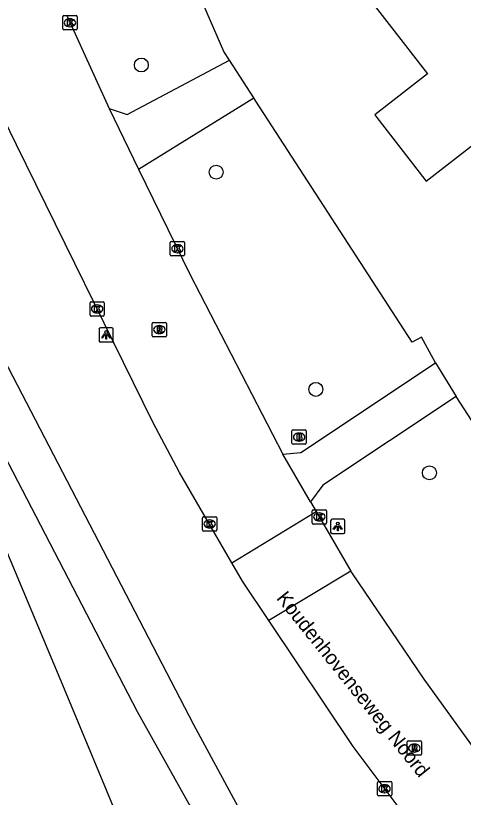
# Model space of a CAD drawing. Extents: x 162417 to 163721, y 384268 to 385416.
# Drawn here: x 163351.6 to 163382.9, y 384915.5 to 384970.3 of the extents above; entities that cross this region are included whole.
import ezdxf

# ---------------------------------------------------------------- set-up
doc = ezdxf.new("R2010")
doc.units = 0
for name, color, linetype in [('IMGEO_Boom', 7, 'Continuous'), ('IMGEO_Brandkraan', 7, 'Continuous'), ('IMGEO_Groenvoorziening', 7, 'Continuous'), ('IMGEO_Kolk', 7, 'Continuous'), ('IMGEO_Lichtpunt', 7, 'Continuous'), ('IMGEO_Loofbos', 7, 'Continuous'), ('IMGEO_Openbare_ruimte_label', 7, 'Continuous'), ('IMGEO_Pand', 7, 'Continuous'), ('IMGEO_Rijbaan_lokaal_gesloten', 7, 'Continuous'), ('IMGEO_Rijbaan_lokaal_open', 7, 'Continuous'), ('IMGEO_Rioolput', 7, 'Continuous'), ('IMGEO_Voetpad_open', 7, 'Continuous')]:
    doc.layers.add(name, color=color, linetype=linetype)

msp = doc.modelspace()

# ---------------------------------------------------------------- linework, layer by layer
at = {"layer": 'IMGEO_Boom'}
for centre in [(163360.375, 384966.821), (163365.617, 384959.319), (163372.593, 384944.113), (163380.546, 384938.265)]:
    msp.add_circle(centre, 0.489, dxfattribs=at)
at = {"layer": 'IMGEO_Brandkraan'}
for p, q in [((163370.923, 384940.346), (163370.923, 384941.198)), ((163370.998, 384941.272), (163371.85, 384941.272)), ((163371.924, 384941.198), (163371.924, 384940.346)), ((163371.411, 384941.052), (163371.436, 384941.052)), ((163371.85, 384940.272), (163370.998, 384940.272)), ((163371.434, 384940.492), (163371.409, 384940.492))]:
    msp.add_line(p, q, dxfattribs=at)
for points in [[(163370.923, 384940.346), (163370.923, 384941.198)], [(163370.998, 384941.272), (163371.85, 384941.272)], [(163371.924, 384941.198), (163371.924, 384940.346)], [(163371.271, 384940.972), (163371.271, 384940.572), (163371.484, 384940.572)], [(163371.502, 384940.972), (163371.271, 384940.972)], [(163371.45, 384940.891), (163371.396, 384940.891), (163371.396, 384940.815)], [(163371.396, 384940.815), (163371.449, 384940.815)], [(163371.458, 384940.739), (163371.396, 384940.739), (163371.396, 384940.658)], [(163371.396, 384940.658), (163371.458, 384940.658)], [(163371.85, 384940.272), (163370.998, 384940.272)]]:
    msp.add_lwpolyline(points, dxfattribs=at)
for centre, radius, start, end in [((163371, 384941.196), 0.0765, 91.552, 178.448), ((163371, 384941.196), 0.0765, 91.552, 178.448), ((163371.848, 384941.196), 0.0765, 1.552, 88.448), ((163371.848, 384941.196), 0.0765, 1.552, 88.448), ((163371.451, 384940.853), 0.0379, 267.8285, 90.9355), ((163371.459, 384940.698), 0.0404, 269.8759, 90.5077), ((163371.49, 384940.823), 0.251, 268.6676, 293.5347), ((163371.506, 384940.827), 0.145, 59.4692, 91.5367), ((163371.531, 384940.874), 0.0922, 285.5137, 58.1501), ((163371.536, 384940.682), 0.105, 301.3115, 78.989), ((163371, 384940.348), 0.0765, 181.552, 268.448), ((163371, 384940.348), 0.0765, 181.552, 268.448), ((163371.848, 384940.348), 0.0765, 271.552, 358.448), ((163371.848, 384940.348), 0.0765, 271.552, 358.448)]:
    msp.add_arc(centre, radius, start, end, dxfattribs=at)
for centre, major_axis, ratio, start_param, end_param in [((163371.41, 384940.772), (-0.387, 0.002), 0.722429, 4.712389, 7.853982), ((163371.435, 384940.772), (-0.39, 0.002), 0.717154, 1.570796, 4.712389)]:
    msp.add_ellipse(centre, major_axis=major_axis, ratio=ratio, start_param=start_param, end_param=end_param, dxfattribs=at)
at = {"layer": 'IMGEO_Groenvoorziening'}
for points in [[(163366.55, 384967.171), (163366.161, 384967.778), (163363.507, 384973.847)], [(163380.971, 384945.978), (163379.982, 384947.768), (163379.349, 384947.426), (163368.391, 384964.299), (163368.242, 384964.531)], [(163394.29, 384925.305), (163382.418, 384943.603)]]:
    msp.add_lwpolyline(points, dxfattribs=at)
at = {"layer": 'IMGEO_Kolk'}
for p, q in [((163354.878, 384969.351), (163354.878, 384970.203)), ((163354.953, 384970.277), (163355.805, 384970.277)), ((163355.879, 384970.203), (163355.879, 384969.351)), ((163355.366, 384970.057), (163355.391, 384970.057)), ((163355.805, 384969.277), (163354.953, 384969.277)), ((163355.389, 384969.497), (163355.364, 384969.497)), ((163362.402, 384953.535), (163362.402, 384954.387)), ((163362.477, 384954.461), (163363.329, 384954.461)), ((163362.89, 384954.241), (163362.915, 384954.241)), ((163363.403, 384954.387), (163363.403, 384953.535)), ((163362.913, 384953.681), (163362.888, 384953.681)), ((163363.329, 384953.461), (163362.477, 384953.461)), ((163356.782, 384949.319), (163356.782, 384950.171)), ((163356.857, 384950.245), (163357.709, 384950.245)), ((163357.27, 384950.025), (163357.295, 384950.025)), ((163357.783, 384950.171), (163357.783, 384949.319)), ((163357.293, 384949.465), (163357.268, 384949.465)), ((163357.709, 384949.245), (163356.857, 384949.245)), ((163372.339, 384934.758), (163372.339, 384935.61)), ((163372.414, 384935.684), (163373.266, 384935.684)), ((163373.34, 384935.61), (163373.34, 384934.758)), ((163364.659, 384934.268), (163364.659, 384935.12)), ((163364.734, 384935.194), (163365.586, 384935.194)), ((163365.66, 384935.12), (163365.66, 384934.268)), ((163372.827, 384935.464), (163372.852, 384935.464)), ((163365.147, 384934.974), (163365.172, 384934.974)), ((163373.266, 384934.684), (163372.414, 384934.684)), ((163372.85, 384934.904), (163372.825, 384934.904)), ((163365.586, 384934.194), (163364.734, 384934.194)), ((163365.17, 384934.414), (163365.145, 384934.414)), ((163376.903, 384915.727), (163376.903, 384916.579)), ((163376.978, 384916.653), (163377.83, 384916.653)), ((163377.904, 384916.579), (163377.904, 384915.727)), ((163377.391, 384916.433), (163377.416, 384916.433)), ((163377.83, 384915.653), (163376.978, 384915.653)), ((163377.414, 384915.873), (163377.389, 384915.873))]:
    msp.add_line(p, q, dxfattribs=at)
for points in [[(163354.878, 384969.351), (163354.878, 384970.203)], [(163354.953, 384970.277), (163355.805, 384970.277)], [(163355.879, 384970.203), (163355.879, 384969.351)], [(163355.199, 384969.977), (163355.322, 384969.977), (163355.322, 384969.826), (163355.452, 384969.977), (163355.616, 384969.977), (163355.47, 384969.826), (163355.623, 384969.577), (163355.471, 384969.577), (163355.386, 384969.741), (163355.322, 384969.674), (163355.322, 384969.577), (163355.199, 384969.577), (163355.199, 384969.977)], [(163355.805, 384969.277), (163354.953, 384969.277)], [(163362.402, 384953.535), (163362.402, 384954.387)], [(163362.477, 384954.461), (163363.329, 384954.461)], [(163363.403, 384954.387), (163363.403, 384953.535)], [(163362.723, 384954.161), (163362.846, 384954.161), (163362.846, 384954.01), (163362.976, 384954.161), (163363.14, 384954.161), (163362.994, 384954.01), (163363.147, 384953.761), (163362.995, 384953.761), (163362.91, 384953.925), (163362.846, 384953.858), (163362.846, 384953.761), (163362.723, 384953.761), (163362.723, 384954.161)], [(163363.329, 384953.461), (163362.477, 384953.461)], [(163356.782, 384949.319), (163356.782, 384950.171)], [(163356.857, 384950.245), (163357.709, 384950.245)], [(163357.103, 384949.945), (163357.226, 384949.945), (163357.226, 384949.794), (163357.356, 384949.945), (163357.52, 384949.945), (163357.374, 384949.794), (163357.527, 384949.545), (163357.375, 384949.545), (163357.29, 384949.709), (163357.226, 384949.642), (163357.226, 384949.545), (163357.103, 384949.545), (163357.103, 384949.945)], [(163357.783, 384950.171), (163357.783, 384949.319)], [(163357.709, 384949.245), (163356.857, 384949.245)], [(163372.339, 384934.758), (163372.339, 384935.61)], [(163372.414, 384935.684), (163373.266, 384935.684)], [(163373.34, 384935.61), (163373.34, 384934.758)], [(163364.659, 384934.268), (163364.659, 384935.12)], [(163364.734, 384935.194), (163365.586, 384935.194)], [(163365.66, 384935.12), (163365.66, 384934.268)], [(163372.66, 384935.384), (163372.783, 384935.384), (163372.783, 384935.233), (163372.913, 384935.384), (163373.077, 384935.384), (163372.931, 384935.233), (163373.084, 384934.984), (163372.932, 384934.984), (163372.847, 384935.148), (163372.783, 384935.081), (163372.783, 384934.984), (163372.66, 384934.984), (163372.66, 384935.384)], [(163364.98, 384934.894), (163365.103, 384934.894), (163365.103, 384934.743), (163365.233, 384934.894), (163365.397, 384934.894), (163365.251, 384934.743), (163365.404, 384934.494), (163365.252, 384934.494), (163365.167, 384934.658), (163365.103, 384934.591), (163365.103, 384934.494), (163364.98, 384934.494), (163364.98, 384934.894)], [(163373.266, 384934.684), (163372.414, 384934.684)], [(163365.586, 384934.194), (163364.734, 384934.194)], [(163376.903, 384915.727), (163376.903, 384916.579)], [(163376.978, 384916.653), (163377.83, 384916.653)], [(163377.904, 384916.579), (163377.904, 384915.727)], [(163377.224, 384916.353), (163377.347, 384916.353), (163377.347, 384916.202), (163377.477, 384916.353), (163377.641, 384916.353), (163377.495, 384916.202), (163377.648, 384915.953), (163377.496, 384915.953), (163377.411, 384916.117), (163377.347, 384916.05), (163377.347, 384915.953), (163377.224, 384915.953), (163377.224, 384916.353)], [(163377.83, 384915.653), (163376.978, 384915.653)]]:
    msp.add_lwpolyline(points, dxfattribs=at)
for centre, start, end in [((163354.955, 384970.201), 91.552, 178.448), ((163354.955, 384970.201), 91.552, 178.448), ((163355.803, 384970.201), 1.552, 88.448), ((163355.803, 384970.201), 1.552, 88.448), ((163354.955, 384969.353), 181.552, 268.448), ((163354.955, 384969.353), 181.552, 268.448), ((163355.803, 384969.353), 271.552, 358.448), ((163355.803, 384969.353), 271.552, 358.448), ((163362.479, 384954.385), 91.552, 178.448), ((163362.479, 384954.385), 91.552, 178.448), ((163363.327, 384954.385), 1.552, 88.448), ((163363.327, 384954.385), 1.552, 88.448), ((163362.479, 384953.537), 181.552, 268.448), ((163362.479, 384953.537), 181.552, 268.448), ((163363.327, 384953.537), 271.552, 358.448), ((163363.327, 384953.537), 271.552, 358.448), ((163356.859, 384950.169), 91.552, 178.448), ((163356.859, 384950.169), 91.552, 178.448), ((163357.707, 384950.169), 1.552, 88.448), ((163357.707, 384950.169), 1.552, 88.448), ((163356.859, 384949.321), 181.552, 268.448), ((163356.859, 384949.321), 181.552, 268.448), ((163357.707, 384949.321), 271.552, 358.448), ((163357.707, 384949.321), 271.552, 358.448), ((163372.416, 384935.608), 91.552, 178.448), ((163372.416, 384935.608), 91.552, 178.448), ((163373.264, 384935.608), 1.552, 88.448), ((163373.264, 384935.608), 1.552, 88.448), ((163364.736, 384935.118), 91.552, 178.448), ((163364.736, 384935.118), 91.552, 178.448), ((163365.584, 384935.118), 1.552, 88.448), ((163365.584, 384935.118), 1.552, 88.448), ((163372.416, 384934.76), 181.552, 268.448), ((163372.416, 384934.76), 181.552, 268.448), ((163373.264, 384934.76), 271.552, 358.448), ((163373.264, 384934.76), 271.552, 358.448), ((163364.736, 384934.27), 181.552, 268.448), ((163364.736, 384934.27), 181.552, 268.448), ((163365.584, 384934.27), 271.552, 358.448), ((163365.584, 384934.27), 271.552, 358.448), ((163376.98, 384916.577), 91.552, 178.448), ((163376.98, 384916.577), 91.552, 178.448), ((163377.828, 384916.577), 1.552, 88.448), ((163377.828, 384916.577), 1.552, 88.448), ((163376.98, 384915.729), 181.552, 268.448), ((163376.98, 384915.729), 181.552, 268.448), ((163377.828, 384915.729), 271.552, 358.448), ((163377.828, 384915.729), 271.552, 358.448)]:
    msp.add_arc(centre, 0.0765, start, end, dxfattribs=at)
for centre, major_axis, ratio, start_param, end_param in [((163355.365, 384969.777), (-0.387, 0.002), 0.722429, 4.712389, 7.853982), ((163355.39, 384969.777), (-0.39, 0.002), 0.717154, 1.570796, 4.712389), ((163362.889, 384953.961), (-0.387, 0.002), 0.722429, 4.712389, 7.853982), ((163362.914, 384953.961), (-0.39, 0.002), 0.717154, 1.570796, 4.712389), ((163357.269, 384949.745), (-0.387, 0.002), 0.722429, 4.712389, 7.853982), ((163357.294, 384949.745), (-0.39, 0.002), 0.717154, 1.570796, 4.712389), ((163372.826, 384935.184), (-0.387, 0.002), 0.722429, 4.712389, 7.853982), ((163372.851, 384935.184), (-0.39, 0.002), 0.717154, 1.570796, 4.712389), ((163365.146, 384934.694), (-0.387, 0.002), 0.722429, 4.712389, 7.853982), ((163365.171, 384934.694), (-0.39, 0.002), 0.717154, 1.570796, 4.712389), ((163377.39, 384916.153), (-0.387, 0.002), 0.722429, 4.712389, 7.853982), ((163377.415, 384916.153), (-0.39, 0.002), 0.717154, 1.570796, 4.712389)]:
    msp.add_ellipse(centre, major_axis=major_axis, ratio=ratio, start_param=start_param, end_param=end_param, dxfattribs=at)
at = {"layer": 'IMGEO_Lichtpunt'}
for p, q in [((163357.412, 384948.33), (163357.412, 384947.523)), ((163357.412, 384948.33), (163357.412, 384947.523)), ((163358.314, 384948.425), (163357.506, 384948.425)), ((163358.314, 384948.425), (163357.506, 384948.425)), ((163358.408, 384947.523), (163358.408, 384948.33)), ((163358.408, 384947.523), (163358.408, 384948.33)), ((163357.506, 384947.429), (163358.314, 384947.429)), ((163357.506, 384947.429), (163358.314, 384947.429)), ((163373.629, 384934.919), (163373.629, 384934.112)), ((163373.629, 384934.919), (163373.629, 384934.112)), ((163374.531, 384935.014), (163373.723, 384935.014)), ((163374.531, 384935.014), (163373.723, 384935.014)), ((163374.625, 384934.112), (163374.625, 384934.919)), ((163374.625, 384934.112), (163374.625, 384934.919)), ((163373.723, 384934.018), (163374.531, 384934.018)), ((163373.723, 384934.018), (163374.531, 384934.018))]:
    msp.add_line(p, q, dxfattribs=at)
for points in [[(163357.786, 384947.994), (163357.825, 384947.966), (163357.637, 384947.704), (163357.599, 384947.731), (163357.786, 384947.994)], [(163357.888, 384947.946), (163357.935, 384947.946), (163357.935, 384947.624), (163357.888, 384947.624), (163357.888, 384947.946)], [(163357.998, 384947.966), (163358.036, 384947.993), (163358.223, 384947.731), (163358.184, 384947.703), (163357.998, 384947.966)], [(163374.003, 384934.583), (163374.042, 384934.555), (163373.854, 384934.293), (163373.816, 384934.32), (163374.003, 384934.583)], [(163374.105, 384934.535), (163374.152, 384934.535), (163374.152, 384934.213), (163374.105, 384934.213), (163374.105, 384934.535)], [(163374.215, 384934.555), (163374.253, 384934.582), (163374.44, 384934.32), (163374.401, 384934.292), (163374.215, 384934.555)]]:
    msp.add_lwpolyline(points, dxfattribs=at)
for centre in [(163357.911, 384948.128), (163374.128, 384934.717)]:
    msp.add_circle(centre, 0.0994, dxfattribs=at)
for centre, start, end in [((163357.506, 384948.33), 90, 180), ((163357.506, 384948.33), 90, 180), ((163358.314, 384948.33), 0, 90), ((163358.314, 384948.33), 0, 90), ((163357.506, 384947.523), 180, 270), ((163357.506, 384947.523), 180, 270), ((163358.314, 384947.523), 270, 0), ((163358.314, 384947.523), 270, 360), ((163373.723, 384934.919), 90, 180), ((163373.723, 384934.919), 90, 180), ((163374.531, 384934.919), 0, 90), ((163374.531, 384934.919), 0, 90), ((163373.723, 384934.112), 180, 270), ((163373.723, 384934.112), 180, 270), ((163374.531, 384934.112), 270, 0), ((163374.531, 384934.112), 270, 360)]:
    msp.add_arc(centre, 0.0946, start, end, dxfattribs=at)
at = {"layer": 'IMGEO_Loofbos'}
msp.add_lwpolyline([(163370.337, 384886.24), (163355.108, 384922.849), (163338.205, 384963.202)], dxfattribs=at)
at = {"layer": 'IMGEO_Pand'}
msp.add_lwpolyline([(163383.993, 384961.544), (163389.969, 384966.169), (163389.817, 384966.363), (163387.465, 384969.38), (163391.542, 384972.558), (163385.708, 384980.043), (163381.669, 384976.895), (163381.023, 384977.723), (163380.856, 384977.937), (163374.9, 384973.327), (163375.046, 384973.139), (163380.414, 384966.203), (163376.718, 384963.343), (163376.874, 384963.141), (163380.225, 384958.812), (163380.314, 384958.697), (163383.993, 384961.544)], dxfattribs=at)
at = {"layer": 'IMGEO_Rijbaan_lokaal_gesloten'}
for points in [[(163355.13, 384970.334), (163358.119, 384963.778)], [(163366.713, 384931.978), (163363.047, 384938.292), (163361.182, 384941.826), (163351.64, 384961.227), (163348.551, 384967.508)], [(163358.119, 384963.778), (163360.184, 384959.531)], [(163360.184, 384959.531), (163363.764, 384952.168), (163370.281, 384939.578)], [(163372.231, 384936.23), (163370.281, 384939.578)], [(163372.231, 384936.23), (163372.616, 384935.569)], [(163383.749, 384918.881), (163380.184, 384923.814), (163375.106, 384931.292), (163375.046, 384931.395)], [(163387.873, 384902.747), (163381.659, 384910.522), (163375.211, 384919.101), (163369.3, 384927.939)]]:
    msp.add_lwpolyline(points, dxfattribs=at)
at = {"layer": 'IMGEO_Rijbaan_lokaal_open'}
for points in [[(163366.713, 384931.978), (163372.616, 384935.569)], [(163372.616, 384935.569), (163375.046, 384931.395)], [(163369.3, 384927.939), (163367.462, 384930.688), (163366.713, 384931.978)], [(163375.046, 384931.395), (163369.3, 384927.939)]]:
    msp.add_lwpolyline(points, dxfattribs=at)
at = {"layer": 'IMGEO_Rioolput'}
for p, q in [((163361.212, 384948.795), (163362.064, 384948.795)), ((163361.137, 384947.869), (163361.137, 384948.721)), ((163361.625, 384948.575), (163361.65, 384948.575)), ((163362.138, 384948.721), (163362.138, 384947.869)), ((163362.064, 384947.795), (163361.212, 384947.795)), ((163361.648, 384948.015), (163361.623, 384948.015)), ((163378.991, 384918.574), (163378.991, 384919.426)), ((163379.066, 384919.5), (163379.918, 384919.5)), ((163379.479, 384919.28), (163379.504, 384919.28)), ((163379.992, 384919.426), (163379.992, 384918.574)), ((163379.502, 384918.72), (163379.477, 384918.72)), ((163379.918, 384918.5), (163379.066, 384918.5))]:
    msp.add_line(p, q, dxfattribs=at)
for points in [[(163361.212, 384948.795), (163362.064, 384948.795)], [(163361.137, 384947.869), (163361.137, 384948.721)], [(163361.726, 384948.493), (163361.474, 384948.495), (163361.474, 384948.095)], [(163361.474, 384948.095), (163361.598, 384948.095), (163361.598, 384948.257), (163361.609, 384948.257)], [(163361.652, 384948.414), (163361.598, 384948.414), (163361.598, 384948.333)], [(163361.598, 384948.333), (163361.65, 384948.333)], [(163361.656, 384948.228), (163361.727, 384948.095), (163361.867, 384948.095), (163361.802, 384948.221)], [(163362.138, 384948.721), (163362.138, 384947.869)], [(163362.064, 384947.795), (163361.212, 384947.795)], [(163378.991, 384918.574), (163378.991, 384919.426)], [(163379.066, 384919.5), (163379.918, 384919.5)], [(163379.58, 384919.198), (163379.328, 384919.2), (163379.328, 384918.8)], [(163379.992, 384919.426), (163379.992, 384918.574)], [(163379.328, 384918.8), (163379.452, 384918.8), (163379.452, 384918.962), (163379.463, 384918.962)], [(163379.506, 384919.119), (163379.452, 384919.119), (163379.452, 384919.038)], [(163379.452, 384919.038), (163379.504, 384919.038)], [(163379.51, 384918.933), (163379.581, 384918.8), (163379.721, 384918.8), (163379.656, 384918.926)], [(163379.918, 384918.5), (163379.066, 384918.5)]]:
    msp.add_lwpolyline(points, dxfattribs=at)
for centre, radius, start, end in [((163361.214, 384948.719), 0.0765, 91.552, 178.448), ((163361.214, 384948.719), 0.0765, 91.552, 178.448), ((163362.062, 384948.719), 0.0765, 1.552, 88.448), ((163362.062, 384948.719), 0.0765, 1.552, 88.448), ((163361.608, 384948.204), 0.0533, 26.0293, 88.6989), ((163361.634, 384948.522), 0.19, 274.7715, 282.9687), ((163361.658, 384948.318), 0.0964, 77.0061, 93.1865), ((163361.672, 384948.375), 0.0378, 276.6634, 79.6772), ((163361.725, 384948.383), 0.109, 350.3612, 89.416), ((163361.723, 384948.383), 0.112, 277.5842, 350.9817), ((163361.707, 384948.168), 0.108, 29.5134, 73.7905), ((163361.214, 384947.871), 0.0765, 181.552, 268.448), ((163361.214, 384947.871), 0.0765, 181.552, 268.448), ((163362.062, 384947.871), 0.0765, 271.552, 358.448), ((163362.062, 384947.871), 0.0765, 271.552, 358.448), ((163379.068, 384919.424), 0.0765, 91.552, 178.448), ((163379.068, 384919.424), 0.0765, 91.552, 178.448), ((163379.579, 384919.088), 0.109, 350.3612, 89.416), ((163379.916, 384919.424), 0.0765, 1.552, 88.448), ((163379.916, 384919.424), 0.0765, 1.552, 88.448), ((163379.462, 384918.909), 0.0533, 26.0293, 88.6989), ((163379.488, 384919.227), 0.19, 274.7715, 282.9687), ((163379.512, 384919.023), 0.0964, 77.0061, 93.1865), ((163379.526, 384919.08), 0.0378, 276.6634, 79.6772), ((163379.577, 384919.088), 0.112, 277.5842, 350.9817), ((163379.561, 384918.873), 0.108, 29.5134, 73.7905), ((163379.068, 384918.576), 0.0765, 181.552, 268.448), ((163379.068, 384918.576), 0.0765, 181.552, 268.448), ((163379.916, 384918.576), 0.0765, 271.552, 358.448), ((163379.916, 384918.576), 0.0765, 271.552, 358.448)]:
    msp.add_arc(centre, radius, start, end, dxfattribs=at)
for centre, major_axis, ratio, start_param, end_param in [((163361.624, 384948.295), (-0.387, 0.002), 0.722429, 4.712389, 7.853982), ((163361.649, 384948.295), (-0.39, 0.002), 0.717154, 1.570796, 4.712389), ((163379.478, 384919), (-0.387, 0.002), 0.722429, 4.712389, 7.853982), ((163379.503, 384919), (-0.39, 0.002), 0.717154, 1.570796, 4.712389)]:
    msp.add_ellipse(centre, major_axis=major_axis, ratio=ratio, start_param=start_param, end_param=end_param, dxfattribs=at)
at = {"layer": 'IMGEO_Voetpad_open'}
for points in [[(163358.119, 384963.778), (163359.376, 384963.356), (163366.55, 384967.171)], [(163368.242, 384964.531), (163366.55, 384967.171)], [(163341.262, 384964.426), (163344.699, 384957.814), (163364.022, 384920.643), (163374.727, 384900.875), (163379.128, 384892.265)], [(163360.184, 384959.531), (163368.242, 384964.531)], [(163377.046, 384890.814), (163369.878, 384904.051), (163360.118, 384921.532), (163347.204, 384946.37), (163338.574, 384963.356), (163338.205, 384963.202)], [(163370.281, 384939.578), (163371.539, 384939.695), (163380.971, 384945.978)], [(163380.971, 384945.978), (163382.418, 384943.603)], [(163382.418, 384943.603), (163373.08, 384937.416), (163372.231, 384936.23)]]:
    msp.add_lwpolyline(points, dxfattribs=at)

# ---------------------------------------------------------------- texts
at = {"layer": 'IMGEO_Openbare_ruimte_label'}
msp.add_text('Koudenhovenseweg Noord', height=1, rotation=308.624, dxfattribs=at).set_placement((163369.786, 384929.475))

doc.saveas('drawing.dxf')
